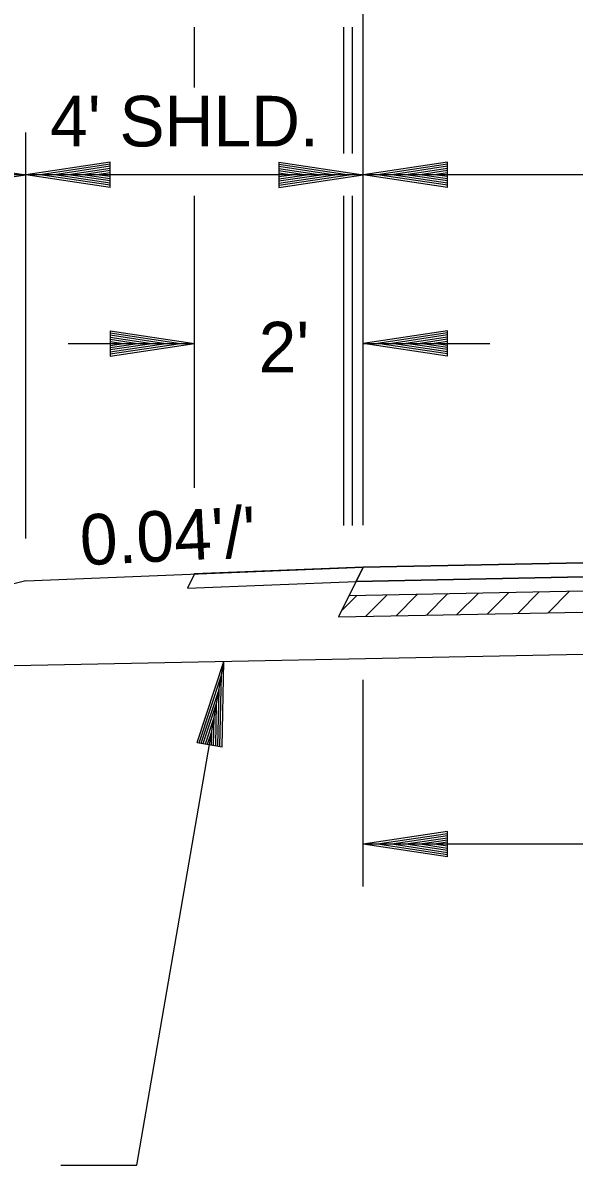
# Model space of a CAD drawing. Extents: x 138 to 3619, y -519 to 1449.
# Drawn here: x 460.9 to 526.3, y 468 to 603.4 of the extents above; entities that cross this region are included whole.
import ezdxf

# ---------------------------------------------------------------- set-up
doc = ezdxf.new("R2010")
doc.units = 0
doc.layers.add('R_Annotation', color=7, linetype='Continuous')
doc.layers.add('R_Dimension', color=7, linetype='Continuous')

msp = doc.modelspace()

# ---------------------------------------------------------------- linework, layer by layer
at = {"layer": 'R_Annotation'}
for p, q in [((501.26, 538.86), (611.26, 541.06)), ((500.42, 537.17), (611.26, 539.39)), ((461.26, 537.26), (501.26, 538.86)), ((481.26, 538.06), (480.41, 536.36)), ((501.26, 538.86), (498.32, 532.97)), ((499.58, 535.49), (611.26, 537.72)), ((461.26, 537.26), (381.26, 517.26)), ((480.41, 536.36), (500.41, 537.16)), ((498.32, 532.97), (611.26, 535.22)), ((417.63, 526.35), (611.26, 530.22))]:
    msp.add_line(p, q, dxfattribs=at)
at = {"layer": 'R_Dimension'}
for p, q in [((501.26, 585.39), (501.26, 610.39)), ((481.25, 595.74), (481.25, 602.89)), ((498.95, 587.89), (498.95, 602.89)), ((500, 587.89), (500, 602.89)), ((461.26, 542.26), (461.26, 590.39)), ((451.26, 586.89), (461.26, 585.39)), ((471.26, 586.89), (461.26, 585.39)), ((471.26, 586.64), (462.93, 585.39)), ((471.26, 586.39), (464.65, 585.39)), ((471.26, 583.89), (471.26, 586.89)), ((491.26, 586.89), (501.26, 585.39)), ((491.26, 586.89), (491.26, 583.89)), ((491.26, 586.64), (499.59, 585.39)), ((491.26, 586.39), (497.87, 585.39)), ((511.26, 586.89), (501.26, 585.39)), ((511.26, 586.64), (502.93, 585.39)), ((511.26, 586.39), (504.65, 585.39)), ((511.26, 583.89), (511.26, 586.89)), ((804.9, 585.39), (417.63, 585.39)), ((451.26, 583.89), (461.26, 585.39)), ((471.26, 583.89), (461.26, 585.39)), ((471.26, 584.14), (462.93, 585.39)), ((471.26, 584.4), (464.65, 585.39)), ((471.26, 586.14), (466.32, 585.39)), ((471.26, 584.65), (466.32, 585.39)), ((471.26, 585.88), (468.01, 585.39)), ((471.26, 584.91), (468.01, 585.39)), ((471.26, 585.63), (469.68, 585.39)), ((471.26, 585.16), (469.68, 585.39)), ((491.26, 586.14), (496.21, 585.39)), ((491.26, 585.88), (494.51, 585.39)), ((491.26, 585.63), (492.84, 585.39)), ((491.26, 583.89), (501.26, 585.39)), ((491.26, 584.9), (494.51, 585.39)), ((491.26, 584.4), (497.87, 585.39)), ((491.26, 584.14), (499.59, 585.39)), ((491.26, 584.65), (496.21, 585.39)), ((491.26, 585.16), (492.84, 585.39)), ((501.26, 543.86), (501.26, 585.39)), ((511.26, 583.89), (501.26, 585.39)), ((511.26, 584.14), (502.93, 585.39)), ((511.26, 584.4), (504.65, 585.39)), ((511.26, 586.14), (506.32, 585.39)), ((511.26, 584.65), (506.32, 585.39)), ((511.26, 585.88), (508.01, 585.39)), ((511.26, 584.91), (508.01, 585.39)), ((511.26, 585.63), (509.68, 585.39)), ((511.26, 585.16), (509.68, 585.39)), ((481.25, 548.29), (481.25, 582.89)), ((498.95, 543.8), (498.95, 582.89)), ((500, 543.8), (500, 582.89)), ((471.25, 566.89), (481.25, 565.39)), ((471.25, 566.89), (471.25, 563.89)), ((471.25, 566.64), (479.58, 565.39)), ((471.25, 566.39), (477.86, 565.39)), ((471.25, 566.14), (476.19, 565.39)), ((511.26, 566.89), (501.26, 565.39)), ((511.26, 566.64), (502.93, 565.39)), ((511.26, 566.39), (504.65, 565.39)), ((511.26, 566.14), (506.32, 565.39)), ((511.26, 563.89), (511.26, 566.89)), ((466.25, 565.39), (481.25, 565.39)), ((471.25, 565.88), (474.5, 565.39)), ((471.25, 565.63), (472.83, 565.39)), ((471.25, 563.89), (481.25, 565.39)), ((471.25, 564.9), (474.5, 565.39)), ((471.25, 564.4), (477.86, 565.39)), ((471.25, 564.14), (479.58, 565.39)), ((471.25, 564.65), (476.19, 565.39)), ((471.25, 565.16), (472.83, 565.39)), ((511.26, 563.89), (501.26, 565.39)), ((501.26, 565.39), (516.26, 565.39)), ((511.26, 564.14), (502.93, 565.39)), ((511.26, 564.4), (504.65, 565.39)), ((511.26, 564.65), (506.32, 565.39)), ((511.26, 565.88), (508.01, 565.39)), ((511.26, 564.91), (508.01, 565.39)), ((511.26, 565.63), (509.68, 565.39)), ((511.26, 565.16), (509.68, 565.39)), ((611.26, 541.06), (501.26, 538.86)), ((500.41, 537.16), (611.26, 539.39)), ((611.26, 539.39), (500.41, 537.16)), ((481.26, 538.06), (480.41, 536.36)), ((501.26, 538.86), (481.26, 538.06)), ((499.58, 535.49), (611.26, 537.72)), ((500.41, 537.16), (501.26, 538.86)), ((501.26, 538.86), (500.41, 537.16)), ((480.41, 536.36), (500.41, 537.16)), ((500.41, 537.16), (499.58, 535.49)), ((498.7, 533.73), (500.48, 535.51)), ((501.54, 533.03), (504.09, 535.58)), ((505.14, 533.1), (507.7, 535.65)), ((508.75, 533.17), (511.3, 535.73)), ((512.36, 533.25), (514.91, 535.8)), ((515.97, 533.32), (518.52, 535.87)), ((519.58, 533.39), (522.13, 535.94)), ((523.18, 533.46), (525.73, 536.01)), ((481.55, 518.1), (484.74, 527.69)), ((484.51, 517.58), (484.74, 527.69)), ((481.8, 518.05), (484.45, 526.05)), ((484.26, 517.63), (484.45, 526.05)), ((501.26, 501.02), (501.26, 525.52)), ((482.05, 518.01), (484.16, 524.35)), ((484.01, 517.67), (484.16, 524.35)), ((482.29, 517.97), (483.87, 522.71)), ((483.76, 517.71), (483.87, 522.71)), ((482.55, 517.92), (483.58, 521.04)), ((483.51, 517.76), (483.58, 521.04)), ((482.8, 517.88), (483.3, 519.4)), ((483.26, 517.8), (483.3, 519.4)), ((481.55, 518.1), (484.51, 517.58)), ((511.26, 507.52), (501.26, 506.02)), ((511.26, 507.27), (502.93, 506.02)), ((511.26, 507.01), (504.65, 506.02)), ((511.26, 506.76), (506.32, 506.02)), ((511.26, 506.51), (508.01, 506.02)), ((511.26, 504.52), (511.26, 507.52)), ((511.26, 504.52), (501.26, 506.02)), ((721.26, 506.02), (501.26, 506.02)), ((511.26, 504.77), (502.93, 506.02)), ((511.26, 505.02), (504.65, 506.02)), ((511.26, 505.27), (506.32, 506.02)), ((511.26, 505.53), (508.01, 506.02)), ((511.26, 506.25), (509.68, 506.02)), ((511.26, 505.78), (509.68, 506.02))]:
    msp.add_line(p, q, dxfattribs=at)
msp.add_lwpolyline([(465.41, 467.98), (474.4, 467.98), (484.74, 527.69)], dxfattribs=at)

# ---------------------------------------------------------------- texts
at = {"layer": 'R_Annotation'}
for s, p in [("4' SHLD.", (464.13, 588.74)), ("2'", (488.86, 561.95))]:
    msp.add_text(s, height=6, dxfattribs=at).set_placement(p)
msp.add_text("0.04'/'", height=6, rotation=2.7804, dxfattribs=at).set_placement((467.81, 539.08))

doc.saveas('drawing.dxf')
